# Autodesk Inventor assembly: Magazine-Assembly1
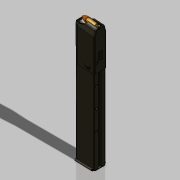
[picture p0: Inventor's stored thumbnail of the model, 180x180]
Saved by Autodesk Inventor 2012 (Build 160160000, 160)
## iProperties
Company: MH Vaaben Teknik
Category: Gun
Created: 2011-12
Part Number: Magazine-Assembly1
Document SubType Name: Assembly
Designer: Michael Høgh
Project: Sten MK II
Material: Steel, Mild
Engineer: MH Vaaben Teknik
Mass: 329.022 g
Surface Area: 886.791 cm^2
Volume: 41.8258 cm^3
Density: 7.8665 g/cm^3
Author: Michael Høgh
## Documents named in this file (8)
- C:\Users\Michael Høgh\Dropbox\Documents\TEC-Ballerup\I - Inventor\2011\Ideer\Sten MK II\Assemblies\Magazine-Assembly1.iam
- C:\Users\Michael Høgh\Dropbox\Documents\TEC-Ballerup\I - Inventor\2011\Ideer\Sten MK II\Parts\Magazine.ipt
- C:\Users\Michael Høgh\Dropbox\Documents\TEC-Ballerup\I - Inventor\2011\Ideer\Sten MK II\Parts\Magazine Bottom Plate.ipt
- C:\Users\Michael Høgh\Dropbox\Documents\TEC-Ballerup\I - Inventor\2011\Ideer\Sten MK II\Parts\Magazine Botton Retainer.ipt
- C:\Users\Michael Høgh\Dropbox\Documents\TEC-Ballerup\I - Inventor\2011\Ideer\Sten MK II\Assemblies\9 mm Parabellum-Assembly1.iam
- C:\Users\Michael Høgh\Dropbox\Documents\TEC-Ballerup\I - Inventor\2011\Ideer\Sten MK II\Assemblies\Magazine Follower-Assembly2.iam
- C:\Users\Michael Høgh\Dropbox\Documents\TEC-Ballerup\I - Inventor\2011\Ideer\Sten MK II\Parts\Magazine Spring - Mounted.ipt
- C:\Users\Michael Høgh\Dropbox\Documents\TEC-Ballerup\I - Inventor\2011\Ideer\Sten MK II\Parts\Magazine Top Cover.ipt
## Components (7 placed, 7 different names)
1. Magazine:1 — Mate:1, Mate:2, Mate:3, Mate:4, Mate:8
2. Magazine Top Cover:1 — Mate:1, Mate:2
3. Magazine Bottom Plate:1 — Mate:3, Mate:4, Mate:5, Mate:6, Mate:7, Angle:1
4. Magazine Botton Retainer:1 — Mate:5, Mate:6, Mate:7, Angle:1
5. Magazine Follower-Assembly2:1 [sub-assembly] — Mate:8
6. 9 mm Parabellum-Assembly1:1 [sub-assembly]
7. Magazine Spring - Mounted:1
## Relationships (9: Mate 8, Angle 1)
- Mate:1: Magazine:1 ↔ Magazine Top Cover:1
- Mate:2: Magazine:1 ↔ Magazine Top Cover:1
- Mate:3: Magazine:1 ↔ Magazine Bottom Plate:1
- Mate:4: Magazine:1 ↔ Magazine Bottom Plate:1
- Mate:5: Magazine Bottom Plate:1 ↔ Magazine Botton Retainer:1
- Mate:6: Magazine Bottom Plate:1 ↔ Magazine Botton Retainer:1
- Mate:7: Magazine Bottom Plate:1 ↔ Magazine Botton Retainer:1
- Mate:8: Magazine:1 ↔ Magazine Follower-Assembly2:1
- Angle:1: Magazine Bottom Plate:1 ↔ Magazine Botton Retainer:1
